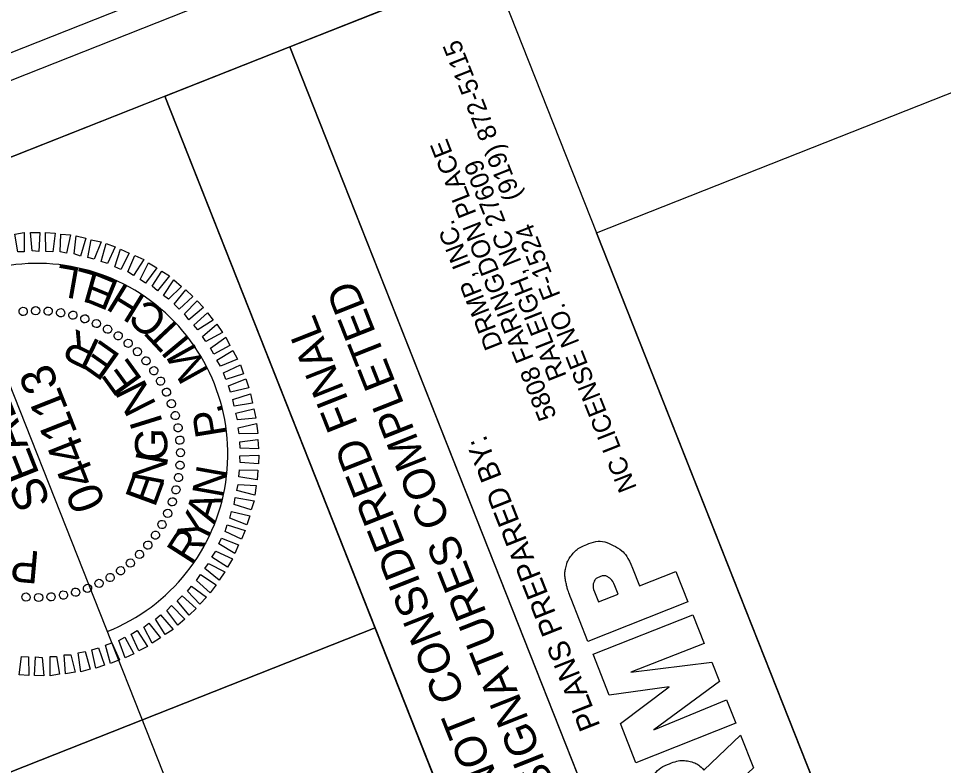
# Model space of a CAD drawing. Extents: x 1250120 to 1251758, y 748130 to 750098.
# Drawn here: x 1250261.4 to 1250423.2, y 749625.9 to 749756.6 of the extents above; entities that cross this region are included whole.
import ezdxf

# ---------------------------------------------------------------- set-up
doc = ezdxf.new("R2010")
doc.units = 0
for name, color, linetype in [('Pattern 1', 7, 'Continuous'), ('Pattern 2', 7, 'Continuous'), ('Scratch_Level_0', 7, 'Continuous'), ('Scratch_Level_1', 7, 'Continuous'), ('Sheet Layout Plan Border', 7, 'Continuous'), ('Sheet Plan And Profile CELL', 7, 'Continuous'), ('Sheet Plot Border Inside CELL', 7, 'Continuous'), ('Sheet Plot Border Outside CELL', 7, 'Continuous'), ('Sheet Professional Seal CELL', 7, 'Continuous'), ('Sheet Sticker Exception Certification CELL', 7, 'Continuous')]:
    doc.layers.add(name, color=color, linetype=linetype)

msp = doc.modelspace()

# ---------------------------------------------------------------- linework, layer by layer
at = {"layer": 'Pattern 1'}
for p, q in [((1250361.91, 749645.36), (1250379.39, 749652.27)), ((1250379.39, 749652.27), (1250381.38, 749647.23)), ((1250381.38, 749647.23), (1250368.54, 749642.25)), ((1250364.75, 749638.18), (1250361.91, 749645.36)), ((1250368.54, 749642.25), (1250382.67, 749643.99)), ((1250382.67, 749643.99), (1250384.01, 749640.6)), ((1250384.01, 749640.6), (1250372.54, 749632.13)), ((1250375.21, 749639.65), (1250364.75, 749638.18)), ((1250366.7, 749633.26), (1250375.21, 749639.65)), ((1250372.54, 749632.13), (1250385.28, 749637.38)), ((1250385.28, 749637.38), (1250386.9, 749633.29)), ((1250369.42, 749626.38), (1250366.7, 749633.26)), ((1250386.9, 749633.29), (1250369.42, 749626.38))]:
    msp.add_line(p, q, dxfattribs=at)
for points in [[(1250368.8, 749660.44), (1250370.03, 749657.34), (1250376.39, 749659.86), (1250378.51, 749654.5), (1250361.03, 749647.59), (1250358.09, 749655.04)], [(1250362.17, 749656.27), (1250362.87, 749654.51), (1250366.29, 749655.86), (1250365.73, 749657.3)], [(1250381.32, 749625.06), (1250387.71, 749631.23), (1250389.98, 749625.49), (1250384.38, 749620.27), (1250385.11, 749618.44), (1250391.73, 749621.06), (1250393.83, 749615.75), (1250376.36, 749608.83), (1250372.98, 749617.37)]]:
    msp.add_lwpolyline(points, dxfattribs=at)
for points in [[(1250358.09, 749655.04), (1250357.63, 749656.2), (1250357.32, 749657.2), (1250357.16, 749658.02), (1250357, 749658.84), (1250356.97, 749659.57), (1250357.08, 749660.2), (1250357.28, 749661.23), (1250357.68, 749662.11), (1250358.3, 749662.84), (1250358.92, 749663.58), (1250359.73, 749664.14), (1250360.74, 749664.54), (1250362.4, 749665.19), (1250363.97, 749665.15), (1250365.46, 749664.4), (1250366.94, 749663.65), (1250368.05, 749662.33), (1250368.8, 749660.44)], [(1250365.73, 749657.3), (1250365.44, 749658.03), (1250365.07, 749658.53), (1250364.6, 749658.81), (1250364.14, 749659.09), (1250363.64, 749659.13), (1250363.1, 749658.91), (1250362.55, 749658.7), (1250362.19, 749658.36), (1250362.03, 749657.91), (1250361.87, 749657.45), (1250361.92, 749656.91), (1250362.17, 749656.27)], [(1250372.98, 749617.37), (1250372.08, 749619.66), (1250371.83, 749621.54), (1250372.22, 749623.01), (1250372.62, 749624.49), (1250373.67, 749625.56), (1250375.38, 749626.24), (1250376.56, 749626.71), (1250377.66, 749626.84), (1250378.68, 749626.64), (1250379.69, 749626.44), (1250380.58, 749625.91), (1250381.32, 749625.06)]]:
    msp.add_open_spline(points, degree=3, dxfattribs=at)
at = {"layer": 'Scratch_Level_0'}
msp.add_lwpolyline([(1250308.89, 749751.61), (1250344.17, 749765.56), (1250417.72, 749579.54), (1250382.44, 749565.59)], close=True, dxfattribs=at)
msp.add_arc((1250264.67, 749680.37), 33.36, 291.5743, 111.5743, dxfattribs=at)
at = {"layer": 'Scratch_Level_1'}
msp.add_line((1250301.74, 749586.63), (1250206.96, 749826.33), dxfattribs=at)
at = {"layer": 'Sheet Layout Plan Border'}
msp.add_lwpolyline([(1251145.64, 748523.25), (1250727.17, 748357.78), (1250285.93, 749473.66), (1250436.11, 749533.04), (1250362.55, 749719.08), (1250630.85, 749825.16)], close=True, dxfattribs=at)
at = {"layer": 'Sheet Plan And Profile CELL'}
msp.add_line((1250219.18, 749608.62), (1250323.75, 749649.97), dxfattribs=at)
for points in [[(1250147.49, 749687.81), (1250699.05, 748292.9), (1251675.49, 748678.99), (1251123.93, 750073.9)], [(1250219.18, 749608.62), (1250182.41, 749701.61), (1250287.03, 749742.98), (1250323.8, 749649.99)], [(1250255.97, 749515.58), (1250219.18, 749608.62), (1250323.8, 749649.99), (1250360.59, 749556.95)]]:
    msp.add_lwpolyline(points, close=True, dxfattribs=at)
at = {"layer": 'Sheet Plot Border Inside CELL'}
msp.add_lwpolyline([(1251734.26, 748537.16), (1251121.66, 750086.44), (1250140.57, 749698.51), (1250753.17, 748149.23)], close=True, dxfattribs=at)
at = {"layer": 'Sheet Plot Border Outside CELL'}
msp.add_lwpolyline([(1251757.64, 748532.43), (1251138.6, 750097.98), (1250120.32, 749695.34), (1250739.35, 748129.79)], close=True, dxfattribs=at)
at = {"layer": 'Sheet Professional Seal CELL'}
for p, q in [((1250262.2, 749705.37), (1250262.2, 749705.37)), ((1250264.42, 749705.49), (1250264.42, 749705.49)), ((1250266.61, 749705.39), (1250266.61, 749705.39)), ((1250268.79, 749705.18), (1250268.79, 749705.18)), ((1250270.92, 749704.67), (1250270.92, 749704.67)), ((1250273.04, 749704.06), (1250273.04, 749704.06)), ((1250275.04, 749703.24), (1250275.04, 749703.24)), ((1250277.04, 749702.26), (1250277.04, 749702.26)), ((1250278.85, 749701.09), (1250278.85, 749701.09)), ((1250280.61, 749699.74), (1250280.61, 749699.74)), ((1250282.26, 749698.3), (1250282.26, 749698.3)), ((1250283.74, 749696.73), (1250283.74, 749696.73)), ((1250285.07, 749695), (1250285.07, 749695)), ((1250286.25, 749693.1), (1250286.25, 749693.1)), ((1250287.32, 749691.21), (1250287.32, 749691.21)), ((1250288.18, 749689.18), (1250288.18, 749689.18)), ((1250288.84, 749687.08), (1250288.84, 749687.08)), ((1250289.31, 749684.96), (1250289.31, 749684.96)), ((1250289.66, 749682.84), (1250289.66, 749682.84)), ((1250264.67, 749680.37), (1250264.67, 749680.37)), ((1250289.79, 749680.63), (1250289.79, 749680.63)), ((1250289.68, 749678.44), (1250289.68, 749678.44)), ((1250289.47, 749676.25), (1250289.47, 749676.25)), ((1250288.97, 749674.12), (1250288.97, 749674.12)), ((1250288.36, 749672), (1250288.36, 749672)), ((1250287.53, 749670), (1250287.53, 749670)), ((1250286.55, 749668), (1250286.55, 749668)), ((1250285.38, 749666.2), (1250285.38, 749666.2)), ((1250284.04, 749664.43), (1250284.04, 749664.43)), ((1250281.03, 749661.3), (1250281.03, 749661.3)), ((1250282.59, 749662.78), (1250282.59, 749662.78)), ((1250279.29, 749659.97), (1250279.29, 749659.97)), ((1250277.4, 749658.79), (1250277.4, 749658.79)), ((1250273.48, 749656.87), (1250273.48, 749656.87)), ((1250275.51, 749657.72), (1250275.51, 749657.72)), ((1250262.73, 749655.36), (1250262.73, 749655.36)), ((1250264.92, 749655.26), (1250264.92, 749655.26)), ((1250267.13, 749655.38), (1250267.13, 749655.38)), ((1250269.25, 749655.73), (1250269.25, 749655.73)), ((1250271.38, 749656.2), (1250271.38, 749656.2))]:
    msp.add_line(p, q, dxfattribs=at)
for points in [[(1250261.27, 749715.75), (1250260.74, 749718.87), (1250262.4, 749719.16), (1250262.39, 749715.77)], [(1250263.78, 749715.94), (1250263.48, 749719.15), (1250265.16, 749719.12), (1250264.96, 749715.81)], [(1250266.19, 749715.82), (1250266.12, 749719.12), (1250267.84, 749719), (1250267.4, 749715.76)], [(1250268.7, 749715.73), (1250268.81, 749718.84), (1250270.53, 749718.72), (1250269.8, 749715.52)], [(1250271.14, 749715.41), (1250271.5, 749718.56), (1250273.17, 749718.15), (1250272.27, 749714.99)], [(1250273.55, 749714.75), (1250274.14, 749717.88), (1250275.84, 749717.53), (1250274.67, 749714.49)], [(1250275.87, 749714.05), (1250276.73, 749717.19), (1250278.34, 749716.64), (1250276.96, 749713.73)], [(1250278.28, 749713.12), (1250279.25, 749716.25), (1250280.78, 749715.51), (1250279.32, 749712.67)], [(1250280.51, 749712.23), (1250281.75, 749715.09), (1250283.31, 749714.41), (1250281.51, 749711.61)], [(1250282.69, 749710.94), (1250284.13, 749713.82), (1250285.6, 749712.95), (1250283.64, 749710.3)], [(1250284.78, 749709.73), (1250286.48, 749712.38), (1250287.84, 749711.53), (1250285.75, 749708.92)], [(1250286.76, 749708.14), (1250288.59, 749710.85), (1250289.9, 749709.71), (1250287.66, 749707.48)], [(1250288.66, 749706.58), (1250290.68, 749709.1), (1250291.9, 749707.92), (1250289.49, 749705.72)], [(1250290.45, 749704.92), (1250292.67, 749707.2), (1250293.78, 749706.02), (1250291.19, 749703.87)], [(1250292.09, 749702.94), (1250294.46, 749705.11), (1250295.45, 749703.83), (1250292.8, 749702.09)], [(1250293.58, 749700.95), (1250296.12, 749703.08), (1250297.07, 749701.63), (1250294.2, 749700.06)], [(1250294.97, 749698.92), (1250297.66, 749700.84), (1250298.4, 749699.36), (1250295.55, 749697.86)], [(1250296.13, 749696.79), (1250298.91, 749698.48), (1250299.72, 749696.98), (1250296.72, 749695.73)], [(1250297.29, 749694.56), (1250300.22, 749695.99), (1250300.78, 749694.44), (1250297.68, 749693.43)], [(1250298.12, 749692.31), (1250301.15, 749693.51), (1250301.71, 749691.95), (1250298.52, 749691.18)], [(1250298.9, 749689.93), (1250302, 749690.94), (1250302.33, 749689.3), (1250299.16, 749688.74)], [(1250299.41, 749687.55), (1250302.55, 749688.31), (1250302.93, 749686.68), (1250299.71, 749686.38)], [(1250299.84, 749684.98), (1250303.05, 749685.71), (1250303.3, 749683.98), (1250299.99, 749683.91)], [(1250300.12, 749682.51), (1250303.28, 749682.95), (1250303.38, 749681.32), (1250300.18, 749681.4)], [(1250300.11, 749680.08), (1250303.46, 749680.17), (1250303.42, 749678.65), (1250300.21, 749678.89)], [(1250300.05, 749677.64), (1250303.25, 749677.56), (1250303.17, 749675.87), (1250299.94, 749676.42)], [(1250299.83, 749675.08), (1250302.97, 749674.87), (1250302.74, 749673.17), (1250299.62, 749673.98)], [(1250299.29, 749672.77), (1250302.63, 749672.21), (1250302.13, 749670.62), (1250299.14, 749671.53)], [(1250298.65, 749670.31), (1250301.89, 749669.6), (1250301.34, 749667.99), (1250298.35, 749669.17)], [(1250297.91, 749667.98), (1250301.08, 749667.03), (1250300.4, 749665.47), (1250297.56, 749666.82)], [(1250296.94, 749665.66), (1250299.92, 749664.52), (1250299.24, 749662.97), (1250296.47, 749664.67)], [(1250295.91, 749663.37), (1250298.85, 749662.06), (1250297.98, 749660.59), (1250295.24, 749662.35)], [(1250294.65, 749661.26), (1250297.5, 749659.75), (1250296.5, 749658.33), (1250293.98, 749660.35)], [(1250293.22, 749659.3), (1250295.96, 749657.53), (1250294.92, 749656.09), (1250292.55, 749658.28)], [(1250291.65, 749657.28), (1250294.31, 749655.32), (1250293.11, 749654.14), (1250290.99, 749656.37)], [(1250290.02, 749655.56), (1250292.5, 749653.36), (1250291.25, 749652.17), (1250289.18, 749654.69)], [(1250288.17, 749653.86), (1250290.5, 749651.5), (1250289.26, 749650.42), (1250287.37, 749653)], [(1250286.23, 749652.23), (1250288.47, 749649.68), (1250287.05, 749648.79), (1250285.38, 749651.52)], [(1250284.22, 749650.79), (1250286.26, 749648.21), (1250284.79, 749647.3), (1250283.35, 749650.12)], [(1250280.03, 749648.33), (1250281.6, 749645.45), (1250280.05, 749644.73), (1250278.95, 749647.79)], [(1250282.15, 749649.49), (1250284, 749646.72), (1250282.47, 749645.96), (1250281.11, 749648.86)], [(1250277.72, 749647.36), (1250279.06, 749644.39), (1250277.48, 749643.77), (1250276.61, 749646.92)], [(1250270.54, 749645.27), (1250271.3, 749642.24), (1250269.6, 749641.94), (1250269.41, 749645.26)], [(1250273.06, 749645.84), (1250273.95, 749642.75), (1250272.3, 749642.31), (1250271.85, 749645.63)], [(1250275.38, 749646.49), (1250276.48, 749643.43), (1250274.91, 749642.91), (1250274.23, 749646.14)], [(1250263.14, 749644.93), (1250263.22, 749641.62), (1250261.5, 749641.75), (1250261.94, 749644.99)], [(1250265.56, 749644.81), (1250265.86, 749641.6), (1250264.18, 749641.63), (1250264.38, 749644.93)], [(1250268.07, 749644.99), (1250268.6, 749641.87), (1250266.94, 749641.59), (1250266.94, 749644.98)]]:
    msp.add_lwpolyline(points, close=True, dxfattribs=at)
for centre, major_axis in [((1250262.23, 749705.33), (-0.07, 0.717)), ((1250264.42, 749705.45), (-0.007, 0.72)), ((1250266.6, 749705.38), (0.056, 0.718)), ((1250268.78, 749705.11), (0.118, 0.71)), ((1250270.92, 749704.66), (0.179, 0.697)), ((1250273.01, 749704.03), (0.239, 0.679)), ((1250275.04, 749703.21), (0.298, 0.656)), ((1250276.99, 749702.22), (0.354, 0.627)), ((1250278.85, 749701.06), (0.407, 0.594)), ((1250280.6, 749699.75), (0.457, 0.556)), ((1250282.22, 749698.28), (0.504, 0.514)), ((1250283.72, 749696.69), (0.547, 0.468)), ((1250285.07, 749694.96), (0.586, 0.419)), ((1250286.26, 749693.13), (0.62, 0.366)), ((1250287.29, 749691.2), (0.649, 0.311)), ((1250288.15, 749689.19), (0.674, 0.253)), ((1250288.83, 749687.11), (0.694, 0.193)), ((1250289.32, 749684.98), (0.708, 0.132)), ((1250289.63, 749682.81), (0.717, 0.07)), ((1250289.75, 749680.62), (0.72, 0.007)), ((1250289.67, 749678.44), (0.718, -0.056)), ((1250289.41, 749676.27), (0.71, -0.118)), ((1250288.96, 749674.13), (0.697, -0.179)), ((1250288.32, 749672.03), (0.679, -0.239)), ((1250287.5, 749670), (0.656, -0.298)), ((1250286.51, 749668.05), (0.627, -0.354)), ((1250285.36, 749666.19), (0.594, -0.407)), ((1250284.04, 749664.45), (0.556, -0.457)), ((1250282.58, 749662.82), (0.514, -0.504)), ((1250280.98, 749661.32), (0.468, -0.547)), ((1250279.26, 749659.97), (0.419, -0.586)), ((1250275.5, 749657.75), (0.311, -0.649)), ((1250277.43, 749658.78), (0.366, -0.62)), ((1250269.27, 749655.72), (0.132, -0.708)), ((1250271.4, 749656.21), (0.193, -0.694)), ((1250273.48, 749656.89), (0.253, -0.674)), ((1250262.73, 749655.37), (-0.056, -0.718)), ((1250264.92, 749655.29), (0.007, -0.72)), ((1250267.1, 749655.41), (0.07, -0.717))]:
    msp.add_ellipse(centre, major_axis=major_axis, ratio=0.999708, dxfattribs=at)
at = {"layer": 'Sheet Sticker Exception Certification CELL'}
for p, q in [((1250287.05, 749742.97), (1250308.9, 749751.62)), ((1250308.89, 749751.61), (1250382.44, 749565.59)), ((1250360.59, 749556.95), (1250287.03, 749742.97))]:
    msp.add_line(p, q, dxfattribs=at)

# ---------------------------------------------------------------- texts
at = {"layer": 'Pattern 2'}
for s, height, p in [('NC LICENSE NO. F-1524    (919) 872-5115', 3.25, (1250369.61, 749674.47)), ('5808 FARINGDON PLACE', 3.25, (1250355.6, 749687)), ('RALEIGH, NC 27609', 3.25, (1250357.34, 749694.04)), ('DRMP, INC.', 3.25, (1250346.19, 749699.38)), ('PLANS PREPARED BY:', 3.75, (1250363.24, 749632.85))]:
    msp.add_text(s, height=height, rotation=111.5743, dxfattribs=at).set_placement(p)
at = {"layer": 'Sheet Professional Seal CELL'}
for s, height, rotation, p in [('L', 5.5, 169.9937, (1250272.45, 749712.88)), ('L', 5.5, 164.1835, (1250275.7, 749711.92)), ('E', 5.5, 157.6006, (1250279.25, 749710.45)), ('H', 5.5, 148.3558, (1250283.89, 749707.72)), ('C', 5.5, 139.483, (1250287.88, 749704.43)), ('T', 5.5, 133.1863, (1250290.38, 749701.74)), ('R', 5.64, 154.0558, (1250275.99, 749700.01)), ('E', 5.64, 144.6984, (1250279.48, 749697.58)), ('I', 5.5, 129.6658, (1250291.64, 749700.12)), ('M', 5.5, 118.9899, (1250294.83, 749694.78)), ('E', 5.64, 125.9861, (1250283.24, 749693.36)), ('044113', 5.998, 111.5743, (1250276.72, 749671.68)), ('N', 5.64, 116.6307, (1250285.62, 749688.98)), ('SEAL', 5.998, 111.5743, (1250267.11, 749671.88)), ('.', 5.5, 105.8097, (1250297.32, 749687.52)), ('I', 5.64, 107.2755, (1250286.71, 749685.81)), ('P', 5.5, 99.2267, (1250297.92, 749683.73)), ('G', 5.64, 88.5646, (1250287.36, 749679.02)), ('N', 5.64, 79.2083, (1250286.66, 749674.66)), ('N', 5.5, 79.8498, (1250297.15, 749672.51)), ('E', 5.64, 69.8512, (1250285.25, 749670.88)), ('A', 5.5, 71.664, (1250295.7, 749667.96)), ('Y', 5.5, 64.3369, (1250293.87, 749664.11)), ('R', 5.5, 57.4104, (1250291.69, 749660.7)), ('P', 5.64, 174.9732, (1250265.29, 749663.31))]:
    msp.add_text(s, height=height, rotation=rotation, dxfattribs=at).set_placement(p)
at = {"layer": 'Sheet Sticker Exception Certification CELL'}
for s, p in [('UNLESS ALL SIGNATURES COMPLETED', (1250372.51, 749578.87)), ('DOCUMENT NOT CONSIDERED FINAL', (1250362.46, 749580.35))]:
    msp.add_text(s, height=5.5, rotation=111.5743, dxfattribs=at).set_placement(p)

doc.saveas('drawing.dxf')
